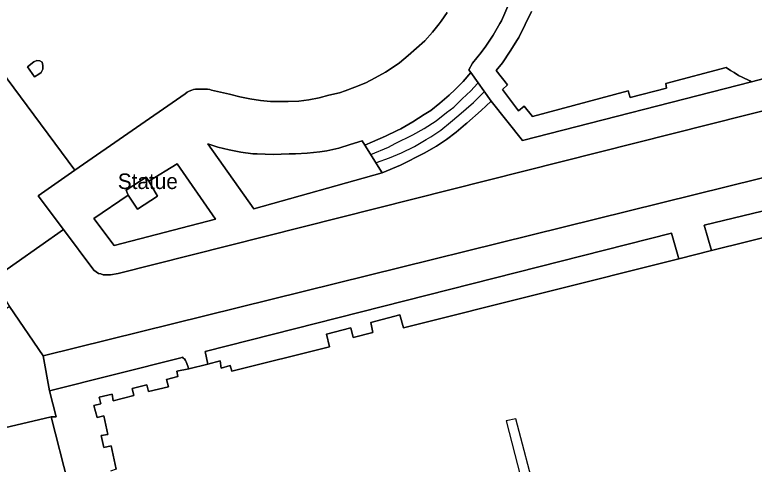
# Model space of a CAD drawing. Extents: x 529240 to 530363, y 179600 to 180767.
# Drawn here: x 529918.6 to 529990.1, y 180233.6 to 180277 of the extents above; entities that cross this region are included whole.
import ezdxf

# ---------------------------------------------------------------- set-up
doc = ezdxf.new("R2010")
doc.units = 0
for name, color, linetype in [('Building', 7, 'Continuous'), ('General surface', 7, 'Continuous'), ('Road Or Track', 7, 'Continuous'), ('Roadside', 7, 'Continuous'), ('Structure', 7, 'Continuous'), ('Unclassified', 7, 'Continuous')]:
    doc.layers.add(name, color=color, linetype=linetype)

msp = doc.modelspace()

# ---------------------------------------------------------------- linework, layer by layer
at = {"layer": 'Building'}
for points in [[(529968.55, 180277.3), (529967.35, 180274.8), (529967.2, 180274.6), (529966.5, 180273.45), (529965.75, 180272.35), (529965.15, 180271.6), (529966.25, 180270.2), (529965.75, 180269.75), (529967.3, 180267.7), (529967.85, 180268.15), (529968.65, 180267.15), (529977.9, 180269.65), (529978.1, 180269), (529981.6, 180269.9), (529981.55, 180270.35), (529987.35, 180271.9), (529987.8, 180271.6), (529988.15, 180271.4), (529988.55, 180271.1), (529988.9, 180270.95), (529989.65, 180270.6), (529989.8, 180270.5), (529992.25, 180271.15)], [(529968.55, 180277.3), (529967.35, 180274.8), (529967.2, 180274.6), (529966.5, 180273.45), (529965.75, 180272.35), (529965.15, 180271.6), (529966.25, 180270.2), (529965.75, 180269.75), (529967.3, 180267.7), (529967.85, 180268.15), (529968.65, 180267.15), (529977.9, 180269.65), (529978.1, 180269), (529981.6, 180269.9), (529981.55, 180270.35), (529987.35, 180271.9), (529987.8, 180271.6), (529988.15, 180271.4), (529988.55, 180271.1), (529988.9, 180270.95), (529989.65, 180270.6), (529989.8, 180270.5)], [(529989.8, 180270.5), (529992.25, 180271.15)], [(530003.2, 180259.8), (530000.6, 180259), (530000.9, 180258.05), (530000, 180257.7), (529985.95, 180254.2)], [(530000, 180257.7), (529985.95, 180254.2), (529982.8, 180253.4), (529956.2, 180246.75), (529955.85, 180248), (529953.05, 180247.25), (529953.25, 180246.3), (529951.35, 180245.8), (529951.1, 180246.75), (529948.75, 180246.15), (529949.05, 180244.9), (529939.6, 180242.55), (529939.45, 180243.1), (529938.6, 180242.85), (529938.5, 180243.55), (529937.3, 180243.25), (529935.45, 180242.8), (529934.3, 180242.55), (529934.4, 180242.05), (529933.3, 180241.75), (529933.5, 180241.05), (529931.55, 180240.6), (529931.4, 180241.25), (529930, 180240.9), (529930.15, 180240.2), (529928.15, 180239.7), (529928.05, 180240.35), (529926.8, 180240.05), (529926.95, 180239.4), (529926.3, 180239.25), (529926.6, 180238.1), (529927.25, 180238.25), (529927.65, 180236.45), (529927, 180236.35), (529927.25, 180235.2), (529927.95, 180235.35), (529928.45, 180233.1)], [(529985.95, 180254.2), (529982.8, 180253.4)], [(529982.8, 180253.4), (529956.2, 180246.75), (529955.85, 180248), (529953.05, 180247.25), (529953.25, 180246.3), (529951.35, 180245.8), (529951.1, 180246.75), (529948.75, 180246.15), (529949.05, 180244.9), (529939.6, 180242.55), (529939.45, 180243.1), (529938.6, 180242.85), (529938.5, 180243.55), (529937.3, 180243.25)], [(529935.45, 180242.8), (529934.3, 180242.55), (529934.4, 180242.05), (529933.3, 180241.75), (529933.5, 180241.05), (529931.55, 180240.6), (529931.4, 180241.25), (529930, 180240.9), (529930.15, 180240.2), (529928.15, 180239.7), (529928.05, 180240.35), (529926.8, 180240.05), (529926.95, 180239.4), (529926.3, 180239.25), (529926.6, 180238.1), (529927.25, 180238.25), (529927.65, 180236.45), (529927, 180236.35), (529927.25, 180235.2), (529927.95, 180235.35), (529928.45, 180233.1), (529927.9, 180232.9)], [(529937.3, 180243.25), (529935.45, 180242.8)], [(529922.15, 180238.15), (529914.35, 180236.3), (529888.1, 180217.5)], [(529923.8, 180231.7), (529922.15, 180238.15), (529914.35, 180236.3)], [(529923.8, 180231.7), (529922.15, 180238.15)], [(529967.05, 180237.95), (529966.1, 180237.75), (529968.05, 180230.25), (529969, 180230.5), (529967.05, 180237.95)]]:
    msp.add_lwpolyline(points, dxfattribs=at)
msp.add_lwpolyline([(529967.05, 180237.95), (529966.1, 180237.75), (529968.05, 180230.25), (529969, 180230.5)], close=True, dxfattribs=at)
at = {"layer": 'General surface'}
for points in [[(529966.4, 180278.1), (529965.65, 180276.4), (529965.5, 180276.15), (529964.85, 180275), (529964.15, 180273.95), (529963.7, 180273.35), (529962.85, 180272.3), (529962.5, 180271.65), (529962.7, 180271.4), (529964.65, 180268.65), (529967.7, 180264.85), (529989.8, 180270.5), (529989.65, 180270.6), (529988.9, 180270.95), (529988.55, 180271.1), (529988.15, 180271.4), (529987.8, 180271.6), (529987.35, 180271.9), (529981.55, 180270.35), (529981.6, 180269.9), (529978.1, 180269), (529977.9, 180269.65), (529968.65, 180267.15), (529967.85, 180268.15), (529967.3, 180267.7), (529965.75, 180269.75), (529966.25, 180270.2), (529965.15, 180271.6), (529965.75, 180272.35), (529966.5, 180273.45), (529967.2, 180274.6), (529967.35, 180274.8), (529968.55, 180277.3)], [(529928.45, 180233.1), (529927.95, 180235.35), (529927.25, 180235.2), (529927, 180236.35), (529927.65, 180236.45), (529927.25, 180238.25), (529926.6, 180238.1), (529926.3, 180239.25), (529926.95, 180239.4), (529926.8, 180240.05), (529928.05, 180240.35), (529928.15, 180239.7), (529930.15, 180240.2), (529930, 180240.9), (529931.4, 180241.25), (529931.55, 180240.6), (529933.5, 180241.05), (529933.3, 180241.75), (529934.4, 180242.05), (529934.3, 180242.55), (529935.45, 180242.8), (529935.2, 180243.45), (529935.15, 180243.6), (529935.05, 180243.75), (529934.95, 180243.8), (529934.85, 180243.9), (529934.7, 180243.85), (529922, 180240.65), (529922.65, 180238.15), (529922.15, 180238.15), (529923.8, 180231.7)]]:
    msp.add_lwpolyline(points, dxfattribs=at)
for points in [[(529964.65, 180268.65), (529962.7, 180271.4), (529961.95, 180270.55), (529961.2, 180269.75), (529960.6, 180269.2), (529959.7, 180268.45), (529958.85, 180267.75), (529958.2, 180267.35), (529957.1, 180266.65), (529955.95, 180265.95), (529955.6, 180265.8), (529954.45, 180265.25), (529953.2, 180264.7), (529952.45, 180264.4), (529954.15, 180261.7), (529955.9, 180262.45), (529958.2, 180263.6), (529959.4, 180264.3), (529960.35, 180264.95), (529961.3, 180265.65), (529962.2, 180266.4), (529962.3, 180266.5), (529963.7, 180267.75)], [(529954.15, 180261.7), (529952.45, 180264.4), (529952.2, 180264.8), (529951.05, 180264.45), (529949.95, 180264.1), (529948.8, 180263.85), (529948.1, 180263.75), (529946.9, 180263.6), (529945.75, 180263.55), (529945.15, 180263.55), (529943.6, 180263.5), (529942.05, 180263.55), (529941.65, 180263.55), (529940.5, 180263.7), (529939.35, 180263.95), (529938.25, 180264.2), (529937.3, 180264.5), (529941.75, 180258.25)], [(529931.6, 180260.9), (529932.45, 180259.45), (529930.5, 180258.2), (529929.6, 180259.55), (529926.3, 180257.3), (529928.25, 180254.7), (529938.05, 180257.25), (529934.35, 180262.6)], [(530003.2, 180259.8), (530002.8, 180260.9), (530000, 180260.2), (529998.95, 180259.95), (529999.2, 180258.6), (529997.38, 180258.13), (529994.19, 180257.3), (529993.05, 180257), (529992.7, 180258.45), (529985.25, 180256.65), (529985.95, 180254.2), (530000, 180257.7), (530000.9, 180258.05), (530000.6, 180259)], [(529982.8, 180253.4), (529982.1, 180255.9), (529937.05, 180244.45), (529937.3, 180243.25), (529938.5, 180243.55), (529938.6, 180242.85), (529939.45, 180243.1), (529939.6, 180242.55), (529949.05, 180244.9), (529948.75, 180246.15), (529951.1, 180246.75), (529951.35, 180245.8), (529953.25, 180246.3), (529953.05, 180247.25), (529955.85, 180248), (529956.2, 180246.75)], [(529922.15, 180238.15), (529922.65, 180238.15), (529922, 180240.65), (529921.4, 180244.05), (529918.15, 180248.8), (529884.4, 180225.45), (529887.1, 180215.8), (529887.15, 180216.05), (529887.35, 180216.55), (529887.5, 180216.85), (529887.8, 180217.25), (529888.1, 180217.5), (529914.35, 180236.3)], [(529967.05, 180237.95), (529966.1, 180237.75), (529968.05, 180230.25), (529969, 180230.5)]]:
    msp.add_lwpolyline(points, close=True, dxfattribs=at)
at = {"layer": 'Road Or Track'}
for points in [[(529912.63, 180277.86), (529908.6, 180275.1), (529897.71, 180267.52), (529907.51, 180250.3), (529914.1, 180254.9), (529916.45, 180251.4), (529923.34, 180256.24), (529920.9, 180259.5), (529924.45, 180261.96)], [(529921.07, 180272.54), (529921.28, 180272.39), (529921.37, 180272.08), (529921.36, 180271.74), (529921.21, 180271.4), (529920.98, 180271.23), (529920.55, 180270.98), (529919.88, 180271.96), (529920.49, 180272.45), (529920.77, 180272.56)], [(529923.34, 180256.24), (529916.45, 180251.4), (529918.15, 180248.8), (529921.4, 180244.05), (530000, 180263.5), (530002, 180264), (530000.58, 180269.6), (530000.45, 180270.1), (530000, 180270), (529928.65, 180252), (529927.9, 180251.85), (529927.2, 180251.85), (529926.95, 180251.95), (529926.75, 180252), (529926.3, 180252.3)]]:
    msp.add_lwpolyline(points, close=True, dxfattribs=at)
for points in [[(529912.63, 180277.86), (529924.45, 180261.96), (529935.1, 180269.35), (529935.3, 180269.5), (529935.5, 180269.6), (529935.75, 180269.7), (529935.9, 180269.75), (529936.1, 180269.8), (529937.25, 180269.8), (529937.5, 180269.75), (529937.65, 180269.7), (529939.4, 180269.3), (529940.4, 180269.05), (529941.35, 180268.85), (529942.4, 180268.7), (529943.35, 180268.6), (529945.05, 180268.6), (529946.1, 180268.65), (529947.05, 180268.75), (529948.05, 180268.95), (529949, 180269.2), (529950, 180269.45), (529950.55, 180269.65), (529951.5, 180270), (529952.55, 180270.4), (529953.45, 180270.9), (529954.45, 180271.45), (529955.3, 180272), (529955.8, 180272.35), (529956.65, 180273.05), (529958.25, 180274.45), (529959, 180275.3), (529959.65, 180276.1), (529959.85, 180276.35), (529960.4, 180277.2)], [(529924.45, 180261.96), (529935.1, 180269.35), (529935.3, 180269.5), (529935.5, 180269.6), (529935.75, 180269.7), (529935.9, 180269.75), (529936.1, 180269.8), (529937.25, 180269.8), (529937.5, 180269.75), (529937.65, 180269.7), (529939.4, 180269.3), (529940.4, 180269.05), (529941.35, 180268.85), (529942.4, 180268.7), (529943.35, 180268.6), (529945.05, 180268.6), (529946.1, 180268.65), (529947.05, 180268.75), (529948.05, 180268.95), (529949, 180269.2), (529950, 180269.45), (529950.55, 180269.65), (529951.5, 180270), (529952.55, 180270.4), (529953.45, 180270.9), (529954.45, 180271.45), (529955.3, 180272), (529955.8, 180272.35), (529956.65, 180273.05), (529958.25, 180274.45), (529959, 180275.3), (529959.65, 180276.1), (529959.85, 180276.35), (529960.4, 180277.2)], [(529921.07, 180272.54), (529921.28, 180272.39), (529921.37, 180272.08), (529921.36, 180271.74), (529921.21, 180271.4), (529920.98, 180271.23), (529920.55, 180270.98), (529919.88, 180271.96), (529920.49, 180272.45), (529920.77, 180272.56), (529921.07, 180272.54)], [(530000.45, 180270.1), (530000, 180270), (529928.65, 180252), (529927.9, 180251.85), (529927.2, 180251.85), (529926.95, 180251.95), (529926.75, 180252), (529926.3, 180252.3), (529923.34, 180256.24)], [(529921.4, 180244.05), (530000, 180263.5), (530002, 180264)], [(529923.34, 180256.24), (529920.9, 180259.5), (529924.45, 180261.96)], [(529918.15, 180248.8), (529921.4, 180244.05)]]:
    msp.add_lwpolyline(points, dxfattribs=at)
at = {"layer": 'Roadside'}
for points in [[(529992.25, 180271.15), (529989.8, 180270.5), (529967.7, 180264.85), (529964.65, 180268.65), (529963.7, 180267.75), (529962.3, 180266.5), (529962.2, 180266.4), (529961.3, 180265.65), (529960.35, 180264.95), (529959.4, 180264.3), (529958.2, 180263.6), (529955.9, 180262.45), (529954.15, 180261.7), (529941.75, 180258.25), (529937.3, 180264.5), (529938.25, 180264.2), (529939.35, 180263.95), (529940.5, 180263.7), (529941.65, 180263.55), (529942.05, 180263.55), (529943.6, 180263.5), (529945.15, 180263.55), (529945.75, 180263.55), (529946.9, 180263.6), (529948.1, 180263.75), (529948.8, 180263.85), (529949.95, 180264.1), (529951.05, 180264.45), (529952.2, 180264.8), (529952.45, 180264.4), (529953.2, 180264.7), (529954.45, 180265.25), (529955.6, 180265.8), (529955.95, 180265.95), (529957.1, 180266.65), (529958.2, 180267.35), (529958.85, 180267.75), (529959.7, 180268.45), (529960.6, 180269.2), (529961.2, 180269.75), (529961.95, 180270.55), (529962.7, 180271.4), (529962.5, 180271.65), (529962.85, 180272.3), (529963.7, 180273.35), (529964.15, 180273.95), (529964.85, 180275), (529965.5, 180276.15), (529965.65, 180276.4), (529966.4, 180278.1)], [(529960.4, 180277.2), (529959.85, 180276.35), (529959.65, 180276.1), (529959, 180275.3), (529958.25, 180274.45), (529956.65, 180273.05), (529955.8, 180272.35), (529955.3, 180272), (529954.45, 180271.45), (529953.45, 180270.9), (529952.55, 180270.4), (529951.5, 180270), (529950.55, 180269.65), (529950, 180269.45), (529949, 180269.2), (529948.05, 180268.95), (529947.05, 180268.75), (529946.1, 180268.65), (529945.05, 180268.6), (529943.35, 180268.6), (529942.4, 180268.7), (529941.35, 180268.85), (529940.4, 180269.05), (529939.4, 180269.3), (529937.65, 180269.7), (529937.5, 180269.75), (529937.25, 180269.8), (529936.1, 180269.8), (529935.9, 180269.75), (529935.75, 180269.7), (529935.5, 180269.6), (529935.3, 180269.5), (529935.1, 180269.35), (529924.45, 180261.96), (529920.9, 180259.5), (529923.34, 180256.24), (529926.3, 180252.3), (529926.75, 180252), (529926.95, 180251.95), (529927.2, 180251.85), (529927.9, 180251.85), (529928.65, 180252), (530000, 180270)]]:
    msp.add_lwpolyline(points, dxfattribs=at)
for points in [[(529921.07, 180272.54), (529920.77, 180272.56), (529920.49, 180272.45), (529919.88, 180271.96), (529920.55, 180270.98), (529920.98, 180271.23), (529921.21, 180271.4), (529921.36, 180271.74), (529921.37, 180272.08), (529921.28, 180272.39)], [(529921.4, 180244.05), (529922, 180240.65), (529934.7, 180243.85), (529934.85, 180243.9), (529934.95, 180243.8), (529935.05, 180243.75), (529935.15, 180243.6), (529935.2, 180243.45), (529935.45, 180242.8), (529937.3, 180243.25), (529937.05, 180244.45), (529982.1, 180255.9), (529982.8, 180253.4), (529985.95, 180254.2), (529985.25, 180256.65), (529992.7, 180258.45), (529993.82, 180258.72), (529996.97, 180259.48), (529998.95, 180259.95), (530000, 180260.2), (530002.8, 180260.9), (530002, 180264), (530000, 180263.5)], [(529934.35, 180262.6), (529938.05, 180257.25), (529928.25, 180254.7), (529926.3, 180257.3), (529929.6, 180259.55), (529929.4, 180260.05), (529931.35, 180261.3), (529931.6, 180260.9)]]:
    msp.add_lwpolyline(points, close=True, dxfattribs=at)
at = {"layer": 'Structure'}
msp.add_lwpolyline([(529931.6, 180260.9), (529931.35, 180261.3), (529929.4, 180260.05), (529929.6, 180259.55), (529930.5, 180258.2), (529932.45, 180259.45)], close=True, dxfattribs=at)
at = {"layer": 'Unclassified'}
for points in [[(529962.5, 180271.65), (529962.85, 180272.3), (529963.7, 180273.35), (529964.15, 180273.95), (529964.85, 180275), (529965.5, 180276.15), (529965.65, 180276.4), (529966.4, 180278.1), (529966.75, 180278.9), (529967.4, 180280.6), (529967.7, 180281.6), (529968.05, 180283.2), (529968.1, 180283.45), (529968.35, 180285.2), (529968.4, 180285.4), (529968.45, 180286.2), (529968.45, 180286.65), (529969.7, 180287.35)], [(529912.63, 180277.86), (529924.45, 180261.96)], [(529962.7, 180271.4), (529961.95, 180270.55), (529961.2, 180269.75), (529960.6, 180269.2), (529959.7, 180268.45), (529958.85, 180267.75), (529958.2, 180267.35), (529957.1, 180266.65), (529955.95, 180265.95), (529955.6, 180265.8), (529954.45, 180265.25), (529953.2, 180264.7), (529952.45, 180264.4)], [(529962.5, 180271.65), (529962.7, 180271.4)], [(529962.7, 180271.4), (529964.65, 180268.65)], [(529964.65, 180268.65), (529967.7, 180264.85), (529989.8, 180270.5)], [(529953.05, 180263.5), (529954.75, 180264.2), (529955.4, 180264.55), (529957.1, 180265.4), (529958.2, 180266), (529959.35, 180266.75), (529960.35, 180267.55), (529961.05, 180268.05), (529961.85, 180268.85), (529962.7, 180269.65), (529963.35, 180270.35)], [(529953.6, 180262.7), (529954.85, 180263.15), (529956, 180263.65), (529957.25, 180264.25), (529958.4, 180264.95), (529958.85, 180265.2), (529959.8, 180265.85), (529960.75, 180266.6), (529961.55, 180267.3), (529962.95, 180268.5), (529964.05, 180269.6)], [(529954.15, 180261.7), (529955.9, 180262.45), (529958.2, 180263.6), (529959.4, 180264.3), (529960.35, 180264.95), (529961.3, 180265.65), (529962.2, 180266.4), (529962.3, 180266.5), (529963.7, 180267.75), (529964.65, 180268.65)], [(529952.45, 180264.4), (529952.2, 180264.8), (529951.05, 180264.45), (529949.95, 180264.1), (529948.8, 180263.85), (529948.1, 180263.75), (529946.9, 180263.6), (529945.75, 180263.55), (529945.15, 180263.55), (529943.6, 180263.5), (529942.05, 180263.55), (529941.65, 180263.55), (529940.5, 180263.7), (529939.35, 180263.95), (529938.25, 180264.2), (529937.3, 180264.5)], [(529937.3, 180264.5), (529941.75, 180258.25)], [(529952.45, 180264.4), (529954.15, 180261.7)], [(529931.6, 180260.9), (529934.35, 180262.6)], [(529938.05, 180257.25), (529934.35, 180262.6)], [(529931.6, 180260.9), (529931.35, 180261.3), (529929.4, 180260.05)], [(529941.75, 180258.25), (529954.15, 180261.7)], [(529929.6, 180259.55), (529930.5, 180258.2), (529932.45, 180259.45), (529931.6, 180260.9)], [(529929.4, 180260.05), (529929.6, 180259.55)], [(529929.6, 180259.55), (529926.3, 180257.3)], [(529985.95, 180254.2), (529985.25, 180256.65), (529992.7, 180258.45)], [(529926.3, 180257.3), (529928.25, 180254.7), (529938.05, 180257.25)], [(529916.45, 180251.4), (529923.34, 180256.24)], [(529937.3, 180243.25), (529937.05, 180244.45), (529982.1, 180255.9), (529982.8, 180253.4)], [(529921.4, 180244.05), (529922, 180240.65)], [(529922, 180240.65), (529934.7, 180243.85), (529934.85, 180243.9), (529934.95, 180243.8), (529935.05, 180243.75), (529935.15, 180243.6), (529935.2, 180243.45), (529935.45, 180242.8)], [(529922.15, 180238.15), (529922.65, 180238.15), (529922, 180240.65)]]:
    msp.add_lwpolyline(points, dxfattribs=at)

# ---------------------------------------------------------------- texts
at = {"layer": 'Structure'}
msp.add_text('Statue', height=1.5, dxfattribs=at).set_placement((529928.6, 180260.15))

doc.saveas('drawing.dxf')
